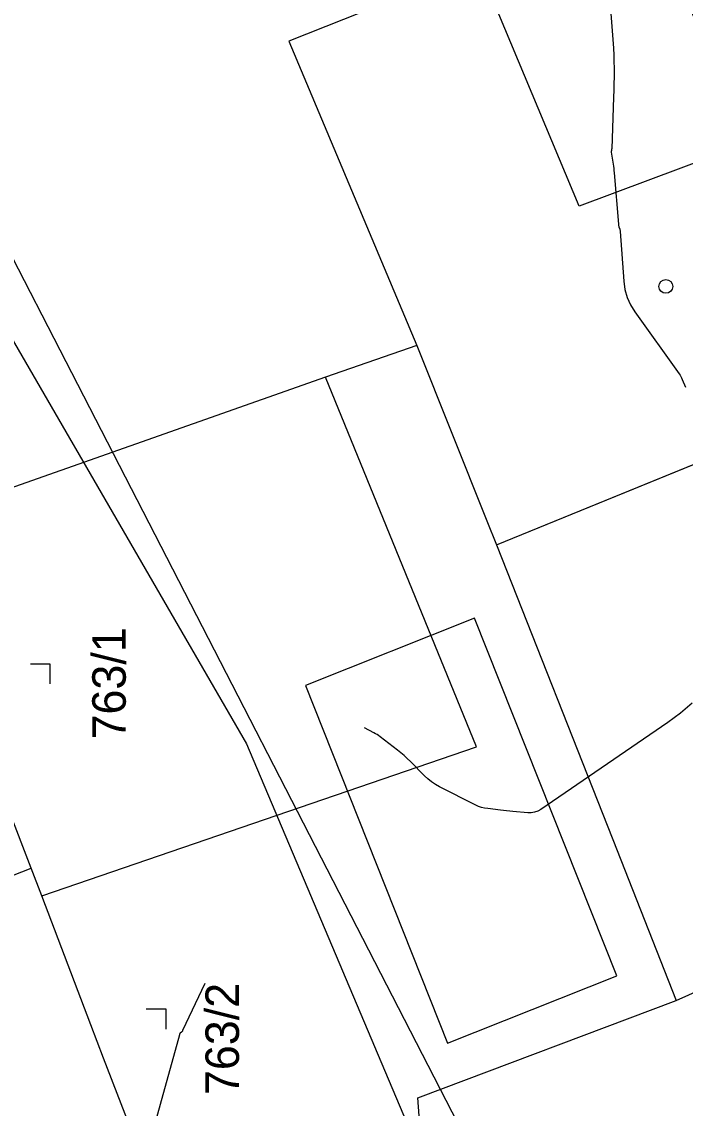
# Model space of a CAD drawing. Extents: x -534481 to -534256, y -1190577 to -1190138.
# Drawn here: x -534420.76 to -534403.93, y -1190505.1 to -1190477.55 of the extents above; entities that cross this region are included whole.
import ezdxf

# ---------------------------------------------------------------- set-up
doc = ezdxf.new("R2010")
doc.units = 0
for name, color, linetype in [('30', 7, 'Continuous'), ('31', 7, 'Continuous'), ('_N_text', 7, 'Continuous'), ('_přístup', 7, 'Continuous'), ('Hranice parcel', 7, 'Continuous'), ('Parcelní čísla', 7, 'Continuous'), ('Polygon budovy', 7, 'Continuous'), ('Značky budov', 7, 'Continuous'), ('Značky kultur', 7, 'Continuous')]:
    doc.layers.add(name, color=color, linetype=linetype)

msp = doc.modelspace()

# ---------------------------------------------------------------- linework, layer by layer
at = {"layer": '30'}
for points in [[(-534405.835, -1190477.127), (-534405.752, -1190478.22), (-534405.748, -1190478.281), (-534405.745, -1190478.342), (-534405.742, -1190478.404), (-534405.741, -1190478.465), (-534405.733, -1190478.83), (-534405.733, -1190478.857), (-534405.733, -1190478.859), (-534405.741, -1190479.224), (-534405.742, -1190479.285), (-534405.744, -1190479.347), (-534405.746, -1190479.408), (-534405.748, -1190479.47), (-534405.796, -1190480.777), (-534405.797, -1190480.784), (-534405.797, -1190480.791), (-534405.798, -1190480.798), (-534405.799, -1190480.804), (-534405.804, -1190480.831), (-534405.805, -1190480.838), (-534405.806, -1190480.845), (-534405.806, -1190480.851), (-534405.805, -1190480.858), (-534405.759, -1190481.166), (-534405.752, -1190481.22), (-534405.745, -1190481.274), (-534405.739, -1190481.328), (-534405.734, -1190481.382), (-534405.624, -1190482.691), (-534405.623, -1190482.707), (-534405.62, -1190482.723), (-534405.616, -1190482.738), (-534405.611, -1190482.754), (-534405.59, -1190482.814), (-534405.585, -1190482.829), (-534405.581, -1190482.845), (-534405.579, -1190482.861), (-534405.577, -1190482.877), (-534405.491, -1190484.133), (-534405.463, -1190484.343), (-534405.406, -1190484.543), (-534405.322, -1190484.733), (-534405.211, -1190484.913), (-534404.084, -1190486.485), (-534404.062, -1190486.518), (-534404.042, -1190486.552), (-534404.023, -1190486.587), (-534404.007, -1190486.624), (-534403.927, -1190486.816)], [(-534403.756, -1190494.829), (-534404.054, -1190495.088), (-534404.374, -1190495.324), (-534407.595, -1190497.527), (-534407.671, -1190497.57), (-534407.751, -1190497.599), (-534407.835, -1190497.612), (-534407.922, -1190497.611), (-534408.299, -1190497.576), (-534408.379, -1190497.568), (-534408.459, -1190497.56), (-534408.539, -1190497.551), (-534408.619, -1190497.543), (-534408.939, -1190497.507), (-534409.018, -1190497.494), (-534409.095, -1190497.475), (-534409.17, -1190497.449), (-534409.243, -1190497.416), (-534410.16, -1190496.953), (-534410.265, -1190496.895), (-534410.364, -1190496.829), (-534410.457, -1190496.754), (-534410.545, -1190496.672), (-534410.9, -1190496.309), (-534410.978, -1190496.233), (-534411.058, -1190496.16), (-534411.14, -1190496.089), (-534411.225, -1190496.022), (-534411.671, -1190495.683), (-534411.707, -1190495.656), (-534411.745, -1190495.631), (-534411.784, -1190495.608), (-534411.824, -1190495.586), (-534412.066, -1190495.46)]]:
    msp.add_lwpolyline(points, dxfattribs=at)
at = {"layer": '31'}
msp.add_lwpolyline([(-534416.117, -1190501.942), (-534416.678, -1190503.136), (-534416.683, -1190503.146), (-534416.689, -1190503.155), (-534416.696, -1190503.163), (-534416.704, -1190503.171), (-534416.736, -1190503.202), (-534416.744, -1190503.21), (-534416.75, -1190503.219), (-534416.755, -1190503.229), (-534416.759, -1190503.239), (-534417.74, -1190506.779)], dxfattribs=at)
at = {"layer": '_N_text'}
msp.add_lwpolyline([(-534406.078, -1190512.511), (-534434.703, -1190456.89), (-534410.94, -1190392.232)], dxfattribs=at)
at = {"layer": '_přístup'}
msp.add_lwpolyline([(-534454.364, -1190460.064), (-534445.984, -1190467.136), (-534433.314, -1190474.1), (-534423.794, -1190480.783), (-534415.053, -1190495.863), (-534409.372, -1190509.296)], dxfattribs=at)
msp.add_lwpolyline([(-534405.667, -1190501.749), (-534409.275, -1190492.679), (-534413.564, -1190494.385), (-534409.956, -1190503.455)], close=True, dxfattribs=at)
at = {"layer": 'Hranice parcel'}
for p, q in [((-534408.72, -1190490.82), (-534395.25, -1190485.32)), ((-534410.74, -1190485.76), (-534413.05, -1190486.57)), ((-534413.05, -1190486.57), (-534423.85, -1190490.37))]:
    msp.add_line(p, q, dxfattribs=at)
for points in [[(-534410.27, -1190476.57), (-534413.98, -1190478.05), (-534410.74, -1190485.76)], [(-534410.74, -1190485.76), (-534408.96, -1190490.21), (-534408.72, -1190490.82)], [(-534420.25, -1190499.72), (-534409.22, -1190495.94), (-534413.05, -1190486.57)], [(-534420.25, -1190499.72), (-534420.52, -1190499.02), (-534423.85, -1190490.37)], [(-534408.72, -1190490.82), (-534405.77, -1190498.29), (-534404.16, -1190502.37)], [(-534404.16, -1190502.37), (-534398.74, -1190499.95), (-534395.53, -1190498.55)], [(-534417.44, -1190507.05), (-534418.68, -1190503.83), (-534419, -1190502.99), (-534420.25, -1190499.72)], [(-534415.58, -1190511.65), (-534410.34, -1190509.87), (-534410.71, -1190504.84), (-534404.16, -1190502.37)]]:
    msp.add_lwpolyline(points, dxfattribs=at)
at = {"layer": 'Polygon budovy'}
for points in [[(-534413.98, -1190478.05), (-534410.74, -1190485.76), (-534408.96, -1190490.21), (-534408.72, -1190490.82), (-534395.25, -1190485.32), (-534400.89, -1190472.11), (-534405.17, -1190474.16), (-534402.3, -1190480.62), (-534406.62, -1190482.23), (-534409.2, -1190476.06), (-534410.27, -1190476.57)], [(-534435.1, -1190485.93), (-534432.31, -1190492.91), (-534429.79, -1190491.88), (-534429.85, -1190491.74), (-534428.8, -1190491.29), (-534424.88, -1190500.72), (-534420.52, -1190499.02), (-534423.85, -1190490.37), (-534424.32, -1190490.54), (-534427.57, -1190482.9)]]:
    msp.add_lwpolyline(points, close=True, dxfattribs=at)
at = {"layer": 'Značky budov'}
msp.add_circle((-534404.422, -1190484.264), 0.175, dxfattribs=at)
at = {"layer": 'Značky kultur'}
for p, q in [((-534420.035, -1190493.842), (-534420.535, -1190493.842)), ((-534420.035, -1190494.342), (-534420.035, -1190493.842)), ((-534417.097, -1190502.595), (-534417.597, -1190502.595)), ((-534417.097, -1190503.095), (-534417.097, -1190502.595))]:
    msp.add_line(p, q, dxfattribs=at)

# ---------------------------------------------------------------- texts
at = {"layer": 'Parcelní čísla'}
for s, p in [('763/1', (-534418.118, -1190495.753)), ('763/2', (-534415.247, -1190504.77))]:
    msp.add_text(s, height=0.85, rotation=90, dxfattribs=at).set_placement(p)

doc.saveas('drawing.dxf')
